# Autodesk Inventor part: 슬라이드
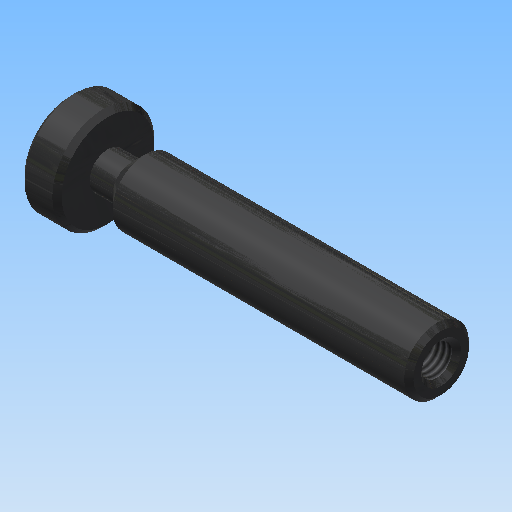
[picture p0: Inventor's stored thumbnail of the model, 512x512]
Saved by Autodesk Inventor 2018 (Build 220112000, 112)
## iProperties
Created: 2015-12
Part Number: 슬라이드
Document SubType Name: Modeling
Designer: mdu
Density: 8.08 g/cm^3
Material: 스테인리스강
Mass: 104.213 g
Surface Area: 46.388 cm^2
Volume: 12.8976 cm^3
Appearance: 진회색
Author: mdu
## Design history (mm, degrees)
sketch "스케치1"
  geometry: L1 (-40, 0)-(40, 0); L2 (-40, 0)-(-40, 11); L3 (-40, 11)-(-32, 11); L4 (-32, 11)-(-32, 4); L5 (-32, 4)-(-27, 4); L6 (-27, 4)-(-24, 7); L7 (-24, 7)-(40, 7); L8 (40, 7)-(40, 0); 2 further points
  constraints: 16 end point, 4 parallel, 2 perpendicular, 1 coincident, 1 horizontal, 1 midpoint
  dimensions: "d0" = 80 distance of L1.start L1.end; "d1" = 22 diameter of L3 L1; "d2" = 14 diameter of L7 L1; "d3" = 8 diameter of L5 L1; "d4" = 8 distance of L2.end L3.end; "d5" = 5 distance of L4.end L5.end; "d6" = 135 deg angle of L6 L5
revolve "회전1" sketch "스케치1" stored, may be unused: angle "d7" = 90 deg
chamfer "모따기1" distance "d8" = 1; stored, may be unused: second distance "d9" = 2, angle "d10" = 45 deg
hole "구멍1" diameter "d13" = 6.647; stored, may be unused: countersink angle "d17" = 90 deg, drill point angle "d19" = 118 deg; dims "d11" = 10, "d12" = 10, "d14" = 9, "d15" = 4, "d16" = 2, "d18" = 12
chamfer "모따기2" distance "d20" = 1; stored, may be unused: second distance "d21" = 2, angle "d22" = 45 deg
node "솔리드1"
